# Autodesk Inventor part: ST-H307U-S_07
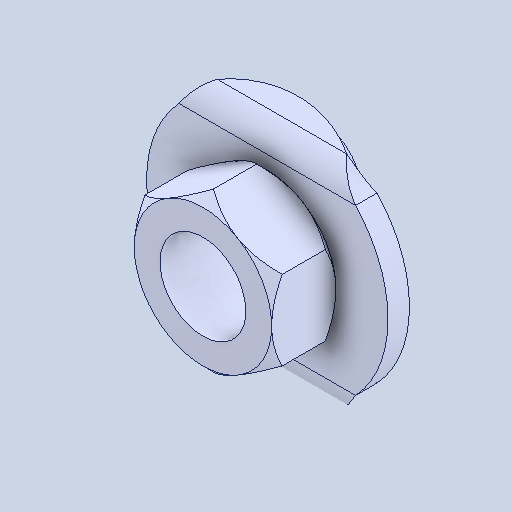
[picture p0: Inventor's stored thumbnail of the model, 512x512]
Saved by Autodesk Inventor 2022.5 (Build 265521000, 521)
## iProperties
Created: 2024-07
Part Number: ST-H307U-S_07
Material: 一般
Document SubType Name: Modeling
Designer: ImaoCorp
Density: 1 g/cm^3
Appearance: 既定
Author: ImaoCorp
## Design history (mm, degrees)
feature "ST-H307U-S_07"
node "ソリッド1"
